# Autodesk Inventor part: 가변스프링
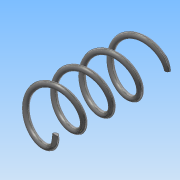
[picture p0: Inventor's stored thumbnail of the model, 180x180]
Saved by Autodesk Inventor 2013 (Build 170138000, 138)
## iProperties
Created: 2015-09
Part Number: 가변스프링
Material: 강철, 탄소
Document SubType Name: Modeling
Designer: Administrator
Density: 7.87 g/cm^3
Mass: 4.92088 g
Surface Area: 12.7468 cm^2
Volume: 0.625271 cm^3
Author: Administrator
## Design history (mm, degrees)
sketch "스케치1"
  geometry: L1 (0, 0)-(8, 0); L2 (8, 42)-(0, 42); L3 (0, 42)-(0, 0); C1 r 1 at (8, 0)
  constraints: 6 end point, 2 parallel, 1 centre point, 1 coincident, 1 horizontal, 1 perpendicular
  dimensions: "d0" = 2 diameter of C1; "d1" = 42 distance of L2.end L1.start (derived); "d3" = 16 diameter of C1.centre L3
feature "코일1" sketch "스케치1" pitch "d4" = 10; turns "d6" = 4; dims "d5" = 42 (= d1), "d7" = 0, angle "d8" = 90 deg, angle "d9" = 90 deg, "d10" = 0, "d11" = 0
sketch "스케치2"
  geometry: L1 (8, 42)-(0, 42) reference; L2 (0, 0)-(8, 0) reference; L3 (11.204, 0)-(-11.365, 0); L4 (-11.365, 0)-(-11.365, 42); L5 (-11.365, 42)-(11.204, 42); L6 (11.204, 42)-(11.204, 0); 1 further point
  constraints: 8 end point, 2 collinear, 2 parallel, 1 horizontal, 1 perpendicular
extrude "돌출1" sketch "스케치2" stored distance "d12" = 0; taper "d13" = 0 deg
node "솔리드1"
